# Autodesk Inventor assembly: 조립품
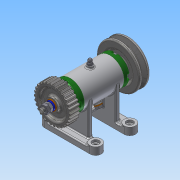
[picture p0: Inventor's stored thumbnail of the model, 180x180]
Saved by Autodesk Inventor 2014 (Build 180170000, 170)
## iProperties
Created: 2015-11
Part Number: 조립품
Document SubType Name: Assembly
Designer: 103-07
Author: 103-07
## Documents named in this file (16)
- C:\Users\103-07\Desktop\451110V1034\조립품.iam
- C:\Users\103-07\Desktop\451110V1034\본체.ipt
- C:\Users\103-07\Desktop\451110V1034\베어링 15 x 32 x 9.ipt
- C:\Users\103-07\Desktop\451110V1034\오일 실 15 25 7.ipt
- C:\Users\103-07\Desktop\451110V1034\커버.ipt
- C:\Users\103-07\Desktop\451110V1034\볼트 M4 x 12.ipt
- C:\Users\103-07\Desktop\451110V1034\축.ipt
- C:\Users\103-07\Desktop\451110V1034\키 3 x 3 x 12.ipt
- C:\Users\103-07\Desktop\451110V1034\V벨트풀리.ipt
- C:\Users\103-07\Desktop\451110V1034\스프링와셔 8.ipt
- C:\Users\103-07\Desktop\451110V1034\와셔 8x17.ipt
- C:\Users\103-07\Desktop\451110V1034\너트 M 8.ipt
- C:\Users\103-07\Desktop\451110V1034\스퍼기어.ipt
- C:\Users\103-07\Desktop\451110V1034\볼트 M 6 x 8.ipt
- C:\Users\103-07\Desktop\451110V1034\와셔 6x11.5.ipt
- C:\Users\103-07\Desktop\451110V1034\니플 M 6 x 0.75.ipt
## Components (11 placed, 3 different names)
1. KS B 2023 6002 - 15 x 32 x 9:1
2. KS B 2023 6002 - 15 x 32 x 9:2
3. V벨트풀리:1 — 각도:3
4. ISO 4762 M4 x 12:1
5. ISO 4762 M4 x 12:3
6. ISO 4762 M4 x 12:4
7. ISO 4762 M4 x 12:5
8. ISO 4762 M4 x 12:2
9. ISO 4762 M4 x 12:6
10. ISO 4762 M4 x 12:7
11. ISO 4762 M4 x 12:8
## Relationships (1: Angle 1)
- 각도:3 [Angle]: V벨트풀리:1
